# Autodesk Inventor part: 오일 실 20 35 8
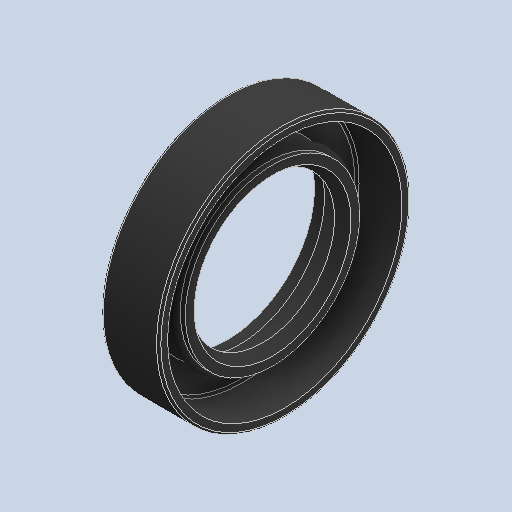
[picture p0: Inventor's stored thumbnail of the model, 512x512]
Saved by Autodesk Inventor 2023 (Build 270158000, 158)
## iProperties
Created: 2026-06
Part Number: 오일 실 20 35 8
Material: 고무
Description: 오일-실
Document SubType Name: Modeling
Designer: 4강의실
Density: 0.93 g/cm^3
Appearance: 기본값
Author: jhkim
Sending System: Autodesk Inventor 2027
Preprocessor: ST-DEVELOPER v20.1
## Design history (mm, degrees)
feature "Solid1"
node "솔리드1"
